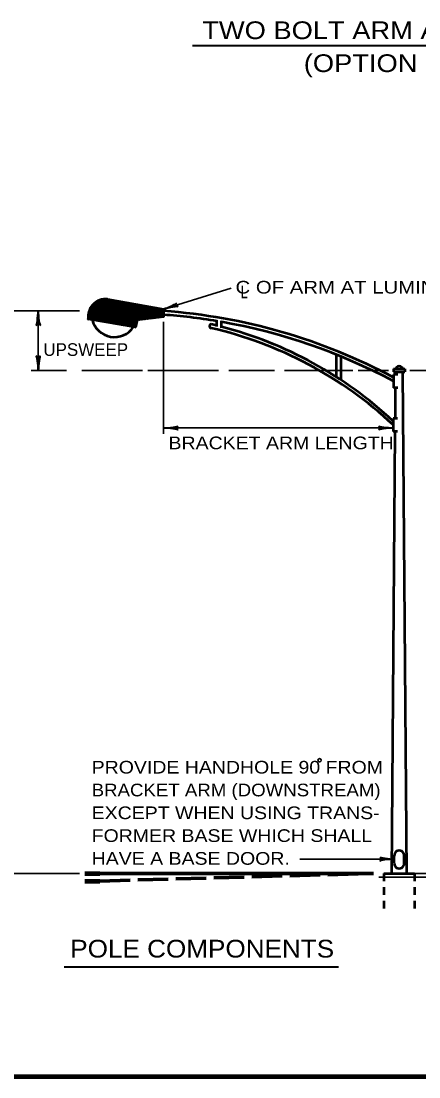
# Model space of a CAD drawing. Extents: x -32 to 824, y -12 to 532.
# Drawn here: x 433 to 527.1, y -0.9 to 249.2 of the extents above; entities that cross this region are included whole.
import ezdxf
from ezdxf.enums import TextEntityAlignment as Align

# ---------------------------------------------------------------- set-up
doc = ezdxf.new("R2010")
doc.units = 0
doc.header["$LTSCALE"] = 1.2
doc.header["$PDMODE"] = 32
doc.header["$PDSIZE"] = 0.6
doc.linetypes.add('LONG_DASHED', pattern=[7.5, 6, -1.5])
doc.linetypes.add('SHORT_DASHED', pattern=[2.7, 1.5, -1.2])
doc.layers.add('1', color=7, linetype='Continuous', lineweight=13)

msp = doc.modelspace()

# ---------------------------------------------------------------- linework, layer by layer
at = {"layer": '1', "lineweight": 40}
for p, q in [((473.514, 243.349), (573.367, 243.349)), ((443.161, 25.212), (508.141, 25.212))]:
    msp.add_line(p, q, dxfattribs=at)
at = {"layer": '1', "lineweight": 35}
for p, q in [((466.689, 180.955), (482.669, 185.875)), ((446.828, 180.505), (424.689, 180.505)), ((437.027, 166.443), (437.027, 180.505)), ((466.689, 177.955), (466.689, 151.384)), ((443.739, 166.443), (435.339, 166.443)), ((461.739, 166.443), (447.339, 166.443)), ((479.739, 166.443), (462.939, 166.443)), ((492.939, 166.443), (482.139, 166.443)), ((511.539, 166.443), (495.339, 166.443)), ((512.739, 166.443), (519.939, 166.443)), ((539.439, 166.443), (525.039, 166.443)), ((521.056, 152.811), (466.689, 152.811)), ((521.382, 50.691), (498.936, 50.691)), ((446.828, 47.305), (424.689, 47.305)), ((517.689, 46.405), (539.289, 46.405)), ((526.089, 47.305), (535.689, 47.305))]:
    msp.add_line(p, q, dxfattribs=at)
at = {"layer": '1', "lineweight": 53}
for p, q in [((448.978, 180.129), (452.06, 183.212)), ((449.015, 180.293), (451.891, 183.17)), ((449.076, 180.482), (451.706, 183.112)), ((449.141, 180.674), (451.515, 183.048)), ((449.238, 180.898), (451.291, 182.951)), ((449.352, 181.139), (451.04, 182.828)), ((449.536, 181.451), (450.734, 182.649)), ((449.594, 180.618), (452.22, 183.244)), ((449.721, 180.618), (452.379, 183.276)), ((449.848, 180.618), (452.52, 183.289)), ((449.976, 180.618), (452.66, 183.303)), ((450.103, 180.618), (452.801, 183.316)), ((450.23, 180.618), (452.928, 183.315)), ((450.357, 180.618), (453.054, 183.314)), ((450.485, 180.618), (453.18, 183.313)), ((450.612, 180.618), (453.301, 183.307)), ((450.739, 180.618), (453.417, 183.296)), ((450.867, 180.618), (453.525, 183.276)), ((450.994, 180.618), (453.633, 183.257)), ((451.121, 180.618), (453.742, 183.238)), ((451.248, 180.618), (453.85, 183.219)), ((451.376, 180.618), (453.958, 183.2)), ((451.503, 180.618), (454.066, 183.181)), ((451.63, 180.618), (454.174, 183.162)), ((451.757, 180.618), (454.283, 183.143)), ((451.885, 180.618), (454.391, 183.124)), ((452.012, 180.618), (454.499, 183.105)), ((452.139, 180.618), (454.607, 183.086)), ((452.267, 180.618), (454.715, 183.067)), ((452.394, 180.618), (454.824, 183.048)), ((452.521, 180.618), (454.932, 183.028)), ((452.648, 180.618), (455.04, 183.009)), ((452.776, 180.618), (455.148, 182.99)), ((452.903, 180.618), (455.256, 182.971)), ((453.03, 180.618), (455.365, 182.952)), ((453.158, 180.618), (455.473, 182.933)), ((453.285, 180.618), (455.581, 182.914)), ((453.412, 180.618), (455.689, 182.895)), ((453.539, 180.618), (455.797, 182.876)), ((453.667, 180.618), (455.906, 182.857)), ((453.794, 180.618), (456.014, 182.838)), ((453.921, 180.618), (456.122, 182.819)), ((454.048, 180.618), (456.23, 182.799)), ((454.176, 180.618), (456.338, 182.78)), ((454.303, 180.618), (456.447, 182.761)), ((454.43, 180.618), (456.555, 182.742)), ((454.558, 180.618), (456.663, 182.723)), ((454.685, 180.618), (456.771, 182.704)), ((454.812, 180.618), (456.879, 182.685)), ((454.939, 180.618), (456.988, 182.666)), ((455.067, 180.618), (457.096, 182.647)), ((455.194, 180.618), (457.204, 182.628)), ((455.321, 180.618), (457.312, 182.609)), ((455.449, 180.618), (457.42, 182.59)), ((455.576, 180.618), (457.529, 182.571)), ((455.703, 180.618), (457.637, 182.551)), ((455.83, 180.618), (457.745, 182.532)), ((448.872, 179.133), (450.132, 180.393)), ((448.874, 179.261), (450.005, 180.393)), ((448.874, 179.007), (450.26, 180.393)), ((448.875, 179.39), (449.878, 180.393)), ((448.883, 179.525), (449.751, 180.393)), ((448.885, 178.891), (450.387, 180.393)), ((448.896, 178.774), (450.514, 180.393)), ((448.899, 179.669), (449.623, 180.393)), ((448.907, 178.658), (450.642, 180.393)), ((448.916, 179.813), (449.567, 180.464)), ((448.942, 179.966), (449.567, 180.591)), ((448.972, 178.596), (450.769, 180.393)), ((449.08, 178.577), (450.896, 180.393)), ((449.188, 178.558), (451.023, 180.393)), ((449.297, 178.539), (451.151, 180.393)), ((449.405, 178.52), (451.278, 180.393)), ((449.513, 178.501), (451.405, 180.393)), ((449.621, 178.482), (451.532, 180.393)), ((449.729, 178.462), (451.66, 180.393)), ((449.838, 178.443), (451.787, 180.393)), ((449.946, 178.424), (451.914, 180.393)), ((450.054, 178.405), (452.042, 180.393)), ((450.102, 182.144), (450.106, 182.148)), ((450.162, 178.386), (452.169, 180.393)), ((450.27, 178.367), (452.296, 180.393)), ((450.379, 178.348), (452.423, 180.393)), ((450.487, 178.329), (452.551, 180.393)), ((450.595, 178.31), (452.678, 180.393)), ((450.703, 178.291), (452.805, 180.393)), ((450.811, 178.272), (452.933, 180.393)), ((450.92, 178.252), (453.06, 180.393)), ((451.028, 178.233), (453.187, 180.393)), ((451.136, 178.214), (453.314, 180.393)), ((451.244, 178.195), (453.442, 180.393)), ((451.352, 178.176), (453.569, 180.393)), ((451.461, 178.157), (453.696, 180.393)), ((451.569, 178.138), (453.823, 180.393)), ((451.677, 178.119), (453.951, 180.393)), ((451.785, 178.1), (454.078, 180.393)), ((451.893, 178.081), (454.205, 180.393)), ((452.002, 178.062), (454.333, 180.393)), ((452.11, 178.043), (454.46, 180.393)), ((452.218, 178.024), (454.587, 180.393)), ((452.326, 178.005), (454.714, 180.393)), ((452.434, 177.985), (454.842, 180.393)), ((452.543, 177.966), (454.969, 180.393)), ((452.651, 177.947), (455.096, 180.393)), ((452.759, 177.928), (455.224, 180.393)), ((452.867, 177.909), (455.351, 180.393)), ((452.975, 177.89), (455.478, 180.393)), ((453.084, 177.871), (455.605, 180.393)), ((453.192, 177.852), (455.733, 180.393)), ((453.3, 177.833), (455.86, 180.393)), ((453.408, 177.814), (455.987, 180.393)), ((453.516, 177.795), (456.115, 180.393)), ((453.625, 177.776), (456.242, 180.393)), ((453.733, 177.756), (456.369, 180.393)), ((453.841, 177.737), (456.496, 180.393)), ((453.949, 177.718), (456.624, 180.393)), ((454.057, 177.699), (456.751, 180.393)), ((454.166, 177.68), (456.878, 180.393)), ((454.274, 177.661), (457.005, 180.393)), ((454.382, 177.642), (457.133, 180.393)), ((454.49, 177.623), (457.26, 180.393)), ((454.598, 177.604), (457.387, 180.393)), ((454.707, 177.585), (457.515, 180.393)), ((454.815, 177.566), (457.642, 180.393)), ((454.923, 177.547), (457.769, 180.393)), ((455.031, 177.528), (457.896, 180.393)), ((455.139, 177.508), (458.024, 180.393)), ((455.248, 177.489), (458.151, 180.393)), ((455.356, 177.47), (458.278, 180.393)), ((455.464, 177.451), (458.406, 180.393)), ((455.572, 177.432), (458.533, 180.393)), ((455.68, 177.413), (458.66, 180.393)), ((455.788, 177.394), (458.787, 180.393)), ((455.897, 177.375), (458.915, 180.393)), ((455.958, 180.618), (457.853, 182.513)), ((456.005, 177.356), (459.042, 180.393)), ((456.085, 180.618), (457.961, 182.494)), ((456.113, 177.337), (459.169, 180.393)), ((456.212, 180.618), (458.07, 182.475)), ((456.221, 177.318), (459.296, 180.393)), ((456.33, 177.299), (459.424, 180.393)), ((456.34, 180.618), (458.178, 182.456)), ((456.438, 177.279), (459.551, 180.393)), ((456.467, 180.618), (458.286, 182.437)), ((456.546, 177.26), (459.678, 180.393)), ((456.594, 180.618), (458.394, 182.418)), ((456.654, 177.241), (459.806, 180.393)), ((456.721, 180.618), (458.502, 182.399)), ((456.762, 177.222), (459.933, 180.393)), ((456.849, 180.618), (458.611, 182.38)), ((456.871, 177.203), (460.06, 180.393)), ((456.976, 180.618), (458.719, 182.361)), ((456.979, 177.184), (460.187, 180.393)), ((457.087, 177.165), (460.315, 180.393)), ((457.103, 180.618), (458.827, 182.342)), ((457.195, 177.146), (460.442, 180.393)), ((457.23, 180.618), (458.935, 182.322)), ((457.303, 177.127), (460.569, 180.393)), ((457.358, 180.618), (459.043, 182.303)), ((457.412, 177.108), (460.697, 180.393)), ((457.485, 180.618), (459.152, 182.284)), ((457.52, 177.089), (460.824, 180.393)), ((457.612, 180.618), (459.26, 182.265)), ((457.628, 177.07), (460.951, 180.393)), ((457.736, 177.05), (461.078, 180.393)), ((457.74, 180.618), (459.368, 182.246)), ((457.844, 177.031), (461.206, 180.393)), ((457.867, 180.618), (459.476, 182.227)), ((457.953, 177.012), (461.333, 180.393)), ((457.994, 180.618), (459.584, 182.208)), ((458.061, 176.993), (461.46, 180.393)), ((458.121, 180.618), (459.693, 182.189)), ((458.169, 176.974), (461.587, 180.393)), ((458.249, 180.618), (459.801, 182.17)), ((458.277, 176.955), (461.715, 180.393)), ((458.376, 180.618), (459.909, 182.151)), ((458.385, 176.936), (461.842, 180.393)), ((458.494, 176.917), (461.969, 180.393)), ((458.503, 180.618), (460.017, 182.132)), ((458.602, 176.898), (462.097, 180.393)), ((458.631, 180.618), (460.125, 182.113)), ((458.71, 176.879), (462.224, 180.393)), ((458.758, 180.618), (460.234, 182.094)), ((458.818, 176.86), (462.351, 180.393)), ((458.885, 180.618), (460.342, 182.074)), ((459.012, 180.618), (460.45, 182.055)), ((459.14, 180.618), (460.558, 182.036)), ((459.267, 180.618), (460.666, 182.017)), ((459.394, 180.618), (460.775, 181.998)), ((459.521, 180.618), (460.883, 181.979)), ((459.649, 180.618), (460.991, 181.96)), ((459.776, 180.618), (461.099, 181.941)), ((459.903, 180.618), (461.207, 181.922)), ((460.031, 180.618), (461.316, 181.903)), ((460.158, 180.618), (461.424, 181.884)), ((460.285, 180.618), (461.532, 181.865)), ((460.412, 180.618), (461.64, 181.846)), ((460.478, 178.393), (462.478, 180.393)), ((460.54, 180.618), (461.748, 181.826)), ((460.623, 178.41), (462.606, 180.393)), ((460.667, 180.618), (461.857, 181.807)), ((460.769, 178.428), (462.733, 180.393)), ((460.794, 180.618), (461.965, 181.788)), ((460.914, 178.446), (462.86, 180.393)), ((460.922, 180.618), (462.073, 181.769)), ((461.049, 180.618), (462.181, 181.75)), ((461.059, 178.464), (462.988, 180.393)), ((461.176, 180.618), (462.289, 181.731)), ((461.204, 178.482), (463.115, 180.393)), ((461.303, 180.618), (462.398, 181.712)), ((461.349, 178.5), (463.242, 180.393)), ((461.431, 180.618), (462.506, 181.693)), ((461.494, 178.517), (463.369, 180.393)), ((461.558, 180.618), (462.614, 181.674)), ((461.639, 178.535), (463.497, 180.393)), ((461.685, 180.618), (462.722, 181.655)), ((461.784, 178.553), (463.624, 180.393)), ((461.812, 180.618), (462.83, 181.636)), ((461.929, 178.571), (463.751, 180.393)), ((461.94, 180.618), (462.939, 181.617)), ((462.067, 180.618), (463.047, 181.597)), ((462.074, 178.589), (463.879, 180.393)), ((462.194, 180.618), (463.155, 181.578)), ((462.22, 178.606), (464.006, 180.393)), ((462.322, 180.618), (463.263, 181.559)), ((462.365, 178.624), (464.133, 180.393)), ((462.449, 180.618), (463.371, 181.54)), ((462.51, 178.642), (464.26, 180.393)), ((462.576, 180.618), (463.48, 181.521)), ((462.655, 178.66), (464.388, 180.393)), ((462.703, 180.618), (463.588, 181.502)), ((462.8, 178.678), (464.515, 180.393)), ((462.831, 180.618), (463.696, 181.483)), ((462.945, 178.695), (464.642, 180.393)), ((462.958, 180.618), (463.804, 181.464)), ((463.085, 180.618), (463.912, 181.445)), ((463.09, 178.713), (464.77, 180.393)), ((463.213, 180.618), (464.021, 181.426)), ((463.235, 178.731), (464.897, 180.393)), ((463.34, 180.618), (464.129, 181.407)), ((463.38, 178.749), (465.024, 180.393)), ((463.467, 180.618), (464.237, 181.388)), ((463.525, 178.767), (465.151, 180.393)), ((463.594, 180.618), (464.345, 181.369)), ((463.67, 178.785), (465.279, 180.393)), ((463.722, 180.618), (464.453, 181.35)), ((463.816, 178.802), (465.406, 180.393)), ((463.849, 180.618), (464.562, 181.33)), ((463.961, 178.82), (465.533, 180.393)), ((463.976, 180.618), (464.67, 181.311)), ((464.103, 180.618), (464.778, 181.292)), ((464.106, 178.838), (465.66, 180.393)), ((464.231, 180.618), (464.886, 181.273)), ((464.251, 178.856), (465.788, 180.393)), ((464.358, 180.618), (464.994, 181.254)), ((464.396, 178.874), (465.915, 180.393)), ((464.485, 180.618), (465.103, 181.235)), ((464.541, 178.891), (466.042, 180.393)), ((464.613, 180.618), (465.211, 181.216)), ((464.686, 178.909), (466.17, 180.393)), ((464.74, 180.618), (465.319, 181.197)), ((464.831, 178.927), (466.689, 180.785)), ((464.867, 180.618), (465.427, 181.178)), ((464.976, 178.945), (466.689, 180.658)), ((464.995, 180.618), (465.535, 181.159)), ((465.121, 178.963), (466.689, 180.531)), ((465.122, 180.618), (465.644, 181.139)), ((465.249, 180.618), (465.752, 181.121)), ((465.266, 178.981), (466.689, 180.403)), ((465.376, 180.618), (465.86, 181.101)), ((465.412, 178.998), (466.689, 180.276)), ((465.504, 180.618), (465.968, 181.082)), ((465.557, 179.016), (466.689, 180.149)), ((465.631, 180.618), (466.076, 181.063)), ((465.702, 179.034), (466.689, 180.022)), ((465.758, 180.618), (466.185, 181.044)), ((465.885, 180.618), (466.293, 181.025)), ((466.013, 180.618), (466.401, 181.006)), ((466.14, 180.618), (466.509, 180.987)), ((466.239, 180.59), (466.617, 180.968)), ((466.239, 180.463), (466.689, 180.913)), ((460.034, 176.645), (448.912, 178.607)), ((458.926, 176.841), (460.425, 178.34)), ((459.035, 176.822), (460.387, 178.174)), ((459.143, 176.802), (460.349, 178.008)), ((459.251, 176.783), (460.311, 177.843)), ((459.359, 176.764), (460.272, 177.678)), ((465.847, 179.052), (466.689, 179.894)), ((465.992, 179.07), (466.689, 179.767)), ((466.137, 179.087), (466.689, 179.64)), ((466.282, 179.105), (466.689, 179.512)), ((466.427, 179.123), (466.689, 179.385)), ((466.572, 179.141), (466.689, 179.258)), ((479.289, 176.811), (479.289, 178.331)), ((480.414, 176.528), (480.414, 178.139)), ((459.467, 176.745), (460.234, 177.512)), ((459.576, 176.726), (460.196, 177.347)), ((459.684, 176.707), (460.158, 177.181)), ((459.792, 176.688), (460.12, 177.016)), ((459.9, 176.669), (460.081, 176.85)), ((460.008, 176.65), (460.043, 176.685)), ((507.639, 164.866), (507.639, 170.153)), ((508.764, 164.131), (508.764, 169.696)), ((522.184, 165.43), (521.134, 165.43)), ((521.134, 165.43), (521.134, 162.28)), ((521.139, 166.78), (523.839, 166.78)), ((521.139, 166.78), (521.139, 166.105)), ((521.139, 166.105), (523.839, 166.105)), ((521.589, 166.105), (521.584, 165.43)), ((524.289, 47.305), (523.389, 166.105)), ((523.839, 166.78), (523.839, 166.105)), ((522.184, 162.28), (521.134, 162.28)), ((521.56, 162.28), (521.506, 155.08)), ((522.106, 155.08), (521.056, 155.08)), ((521.056, 155.08), (521.056, 151.93)), ((521.482, 151.93), (520.689, 47.305)), ((522.106, 151.93), (521.056, 151.93)), ((521.307, 49.701), (521.307, 51.501)), ((523.671, 49.701), (523.671, 51.501)), ((518.889, 47.305), (526.089, 47.305))]:
    msp.add_line(p, q, dxfattribs=at)
at = {"layer": '1', "lineweight": 106}
for p, q in [((448.028, 47.305), (451.628, 47.305)), ((448.028, 45.505), (451.628, 45.505))]:
    msp.add_line(p, q, dxfattribs=at)
at = {"layer": '1', "lineweight": 70}
msp.add_line((451.628, 47.305), (516.428, 47.305), dxfattribs=at)
at = {"layer": '1', "linetype": 'LONG_DASHED', "lineweight": 70}
msp.add_line((451.628, 45.505), (516.428, 47.305), dxfattribs=at)
at = {"layer": '1', "linetype": 'SHORT_DASHED', "lineweight": 53}
for p, q in [((518.889, 47.305), (518.889, 37.705)), ((526.089, 47.305), (526.089, 37.705))]:
    msp.add_line(p, q, dxfattribs=at)
at = {"layer": '1', "lineweight": 158}
msp.add_line((817.469, -0.873), (25.869, -0.873), dxfattribs=at)
at = {"layer": '1', "lineweight": 53}
msp.add_lwpolyline([(453.394, 183.299), (466.689, 180.955), (466.689, 179.155), (460.436, 178.387), (460.034, 176.645)], dxfattribs=at)
msp.add_lwpolyline([(449.567, 180.618), (466.239, 180.618), (466.239, 180.393), (449.567, 180.393)], close=True, dxfattribs=at)
at = {"layer": '1', "lineweight": 35}
msp.add_circle((503.626, 74.112), 0.387, dxfattribs=at)
at = {"layer": '1', "lineweight": 53}
for centre, radius, start, end in [((452.982, 179.206), 4.114, 84.23953, 188.38162), ((456.932, 44.797), 136.059, 61.84402, 85.88743), ((455.078, 179.762), 5.441, 193.94762, 326.05059), ((456.932, 43.897), 136.059, 80.54208, 85.88743), ((456.932, 43.897), 136.059, 61.84402, 80.06146), ((478.014, 176.905), 0.456, 99.37484, 260.62516), ((478.148, 177.202), 0.775, 235.53017, 254.38288), ((457.074, 86.179), 93.534, 76.2603, 77.11012), ((457.074, 85.279), 93.534, 46.83897, 77.11012), ((457.074, 86.179), 93.534, 46.83897, 75.54976), ((522.489, 166.448), 0.955, 20.3922, 159.6078), ((522.489, 51.53), 1.182, 358.58875, 181.41125), ((522.489, 49.657), 1.182, 178.58875, 1.41125)]:
    msp.add_arc(centre, radius, start, end, dxfattribs=at)
at = {"layer": '1', "lineweight": 40}
for centre, major_axis, ratio, start_param, end_param in [((436.773, 179.161), (0.211, 2.108), 0.07063, 3.1407148, 5.41811), ((437.359, 179.196), (-0.187, 2.143), 0.122415, 0.8963533, 3.1415927), ((467.843, 181.657), (-1.993, -0.81), 0.122415, 0.8963533, 3.1415927), ((468.049, 181.108), (2.076, 0.419), 0.07063, 6.2823074, 8.5597026), ((436.696, 167.752), (0.187, -2.143), 0.122415, 0.8963533, 3.1415927), ((437.281, 167.787), (-0.211, -2.108), 0.07063, 3.1407148, 5.41811), ((468.034, 152.557), (-2.108, 0.211), 0.07063, 3.1407148, 5.41811), ((468.034, 152.557), (-2.108, 0.211), 0.07063, 3.1407148, 5.41811), ((467.999, 153.143), (-2.143, -0.187), 0.122415, 0.8963533, 3.1415927), ((467.999, 153.143), (-2.143, -0.187), 0.122415, 0.8963533, 3.1415927), ((519.746, 152.48), (2.143, 0.187), 0.122415, 0.8963533, 3.1415927), ((519.746, 152.48), (2.143, 0.187), 0.122415, 0.8963533, 3.1415927), ((519.711, 153.065), (2.108, -0.211), 0.07063, 3.1407148, 5.41811), ((519.711, 153.065), (2.108, -0.211), 0.07063, 3.1407148, 5.41811), ((520.073, 50.36), (2.143, 0.187), 0.122415, 0.8963533, 3.1415927), ((520.037, 50.945), (2.108, -0.211), 0.07063, 3.1407148, 5.41811)]:
    msp.add_ellipse(centre, major_axis=major_axis, ratio=ratio, start_param=start_param, end_param=end_param, dxfattribs=at)
at = {"layer": '1'}
msp.add_point((448.912, 178.607), dxfattribs=at)

# ---------------------------------------------------------------- texts
at = {"layer": '1', "width": 1.15}
for s, p in [('TWO BOLT ARM ATTACHMENT', (523.759, 244.889)), ('(OPTION NO. 2)', (523.759, 237.089))]:
    msp.add_text(s, height=4.2, dxfattribs=at).set_placement(p, align=Align.CENTER)
at = {"layer": '1'}
for s, height, width, p in [('C OF ARM AT LUMINAIRE END', 3, 1.2, (483.74, 184.632)), ('L', 3, 0.75, (484.943, 183.538)), ('BRACKET ARM LENGTH', 3, 1.15, (467.881, 147.762)), ('PROVIDE HANDHOLE 90 FROM', 3, 1.15, (449.682, 70.963)), ('BRACKET ARM (DOWNSTREAM)', 3, 1.1, (449.682, 65.563)), ('EXCEPT WHEN USING TRANS-', 3, 1.15, (449.682, 60.163)), ('FORMER BASE WHICH SHALL', 3, 1.15, (449.682, 54.763)), ('HAVE A BASE DOOR.', 3, 1.15, (449.682, 49.363)), ('POLE COMPONENTS', 4.2, 1.1, (444.612, 27.389))]:
    msp.add_text(s, height=height, dxfattribs=dict(at, width=width)).set_placement(p)
msp.add_text('UPSWEEP', height=3, dxfattribs=at).set_placement((438.242, 169.862))

doc.saveas('drawing.dxf')
